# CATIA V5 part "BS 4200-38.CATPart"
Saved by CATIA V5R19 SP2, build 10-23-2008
Part number: BS 4200-38
Bounding box of the stored display mesh (mm): x -47.487 to 47.487, y -47.487 to 47.487, z 0 to 141
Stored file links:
  C:\Users\Bora\Desktop\3D Katı model\BS serisi\BS 4200\BS 4200-38.CATPart
  C:\Program Files\Dassault Systemes\B19\intel_a\reffiles\standard\MetricThickPitch.txt
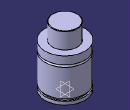
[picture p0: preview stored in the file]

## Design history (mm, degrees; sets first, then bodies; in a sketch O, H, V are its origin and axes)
Body1 (main body)
  Sketch1 on yz-plane, origin (0, 0, 0), H (0, 1, 0), V (0, 0, 1)
    point P2 (47.5, 78.5)
    point P5 (30, 140)
    point P7 (30, 140)
    point P11 (47.5, 83.5)
    point P13 (47.5, 83.5)
    point P14 (47.5, 78.5)
    line L1 (47.5, 13) -> (47.5, 78.5)
    line L2 (44.5, 13) -> (44.5, 8)
    line L3 (30, 140) -> (30, 102)
    arc A1 centre (29, 140) radius 1 from (30, 140) to (29, 141) ccw
    line L4 (47.5, 0) -> (47.5, 8)
    line L5 (47.5, 83.5) -> (47.5, 102)
    arc A2 centre (47.5, 81) radius 2.5 from (47.5, 83.5) to (47.5, 78.5) ccw
    line L6 (29, 141) -> (0, 141)
    point P15 (0, 141)
    line L7 (30, 102) -> (47.5, 102)
    line L8 (0, 0) -> (47.5, 0)
    line L9 (44.5, 13) -> (47.5, 13)
    line L10 (44.5, 8) -> (47.5, 8)
    coincidence: P15 V, P2 P14, P5 P7, P11 P13
    tangency: L6 A1
    horizontal: L7 H, L8 H, L9 H, L10 H
  Shaft1: profile Sketch1, axis Sketch1.V, angle 360
  Sketch2 on face of Shaft1 from Sketch1.L8, origin (0, 0, 0), H (1, 0, 0), V (0, -1, 0)
    point P1 (30, 0)
    distance P1 V = 30
  Hole1: placed by Sketch2, at (30, 0, 0) direction (0, 0, 1), diameter 6.647, depth 7, threaded "M8", thread diameter 8, thread depth 7, pitch 1.25
  CircPattern1: of Hole1, instances 4, angular step 90, axis from xy-plane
